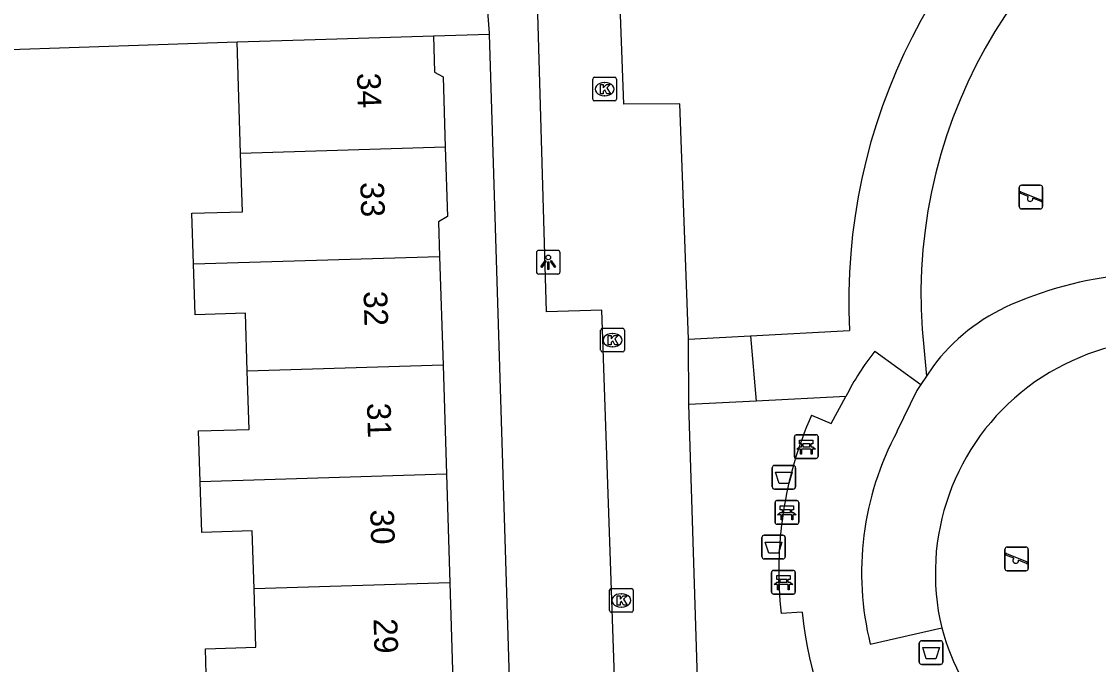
# Model space of a CAD drawing. Extents: x 162250 to 162654, y 380744 to 381605.
# Drawn here: x 162347.75 to 162393.23, y 381155.14 to 381182.3 of the extents above; entities that cross this region are included whole.
import ezdxf

# ---------------------------------------------------------------- set-up
doc = ezdxf.new("R2010")
doc.units = 0
for name, color, linetype in [('IMGEO_Afvalbak', 7, 'Continuous'), ('IMGEO_Bank', 7, 'Continuous'), ('IMGEO_Groenvoorziening', 7, 'Continuous'), ('IMGEO_Kolk', 7, 'Continuous'), ('IMGEO_Lichtpunt', 7, 'Continuous'), ('IMGEO_Pand', 7, 'Continuous'), ('IMGEO_Pand_nummerreeks', 7, 'Continuous'), ('IMGEO_Speelvoorziening', 7, 'Continuous'), ('IMGEO_Voetpad_open', 7, 'Continuous'), ('IMGEO_Woonerf_open', 7, 'Continuous')]:
    doc.layers.add(name, color=color, linetype=linetype)

msp = doc.modelspace()

# ---------------------------------------------------------------- linework, layer by layer
at = {"layer": 'IMGEO_Afvalbak'}
for p, q in [((162379.45, 381162.647), (162379.45, 381163.447)), ((162379.45, 381163.447), (162379.45, 381162.647)), ((162379.55, 381163.547), (162380.34, 381163.547)), ((162380.34, 381163.547), (162379.55, 381163.547)), ((162380.44, 381163.447), (162380.44, 381162.647)), ((162380.44, 381162.647), (162380.44, 381163.447)), ((162380.34, 381162.547), (162379.55, 381162.547)), ((162379.55, 381162.547), (162380.34, 381162.547)), ((162379.013, 381159.698), (162379.013, 381160.498)), ((162379.013, 381160.498), (162379.013, 381159.698)), ((162379.113, 381160.598), (162379.903, 381160.598)), ((162379.903, 381160.598), (162379.113, 381160.598)), ((162380.003, 381160.498), (162380.003, 381159.698)), ((162380.003, 381159.698), (162380.003, 381160.498)), ((162379.903, 381159.598), (162379.113, 381159.598)), ((162379.113, 381159.598), (162379.903, 381159.598)), ((162385.764, 381156.138), (162386.554, 381156.138)), ((162386.554, 381156.138), (162385.764, 381156.138)), ((162385.664, 381155.238), (162385.664, 381156.038)), ((162385.664, 381156.038), (162385.664, 381155.238)), ((162386.654, 381156.038), (162386.654, 381155.238)), ((162386.654, 381155.238), (162386.654, 381156.038)), ((162386.554, 381155.138), (162385.764, 381155.138)), ((162385.764, 381155.138), (162386.554, 381155.138))]:
    msp.add_line(p, q, dxfattribs=at)
for points in [[(162379.593, 381163.261), (162380.297, 381163.261), (162380.148, 381162.791), (162379.742, 381162.791), (162379.593, 381163.261)], [(162379.156, 381160.312), (162379.86, 381160.312), (162379.711, 381159.842), (162379.305, 381159.842), (162379.156, 381160.312)], [(162385.807, 381155.852), (162386.511, 381155.852), (162386.362, 381155.382), (162385.956, 381155.382), (162385.807, 381155.852)]]:
    msp.add_lwpolyline(points, dxfattribs=at)
for centre, start, end in [((162379.55, 381163.447), 90, 180), ((162379.55, 381163.447), 90, 180), ((162380.34, 381163.447), 0, 90), ((162380.34, 381163.447), 360, 90), ((162379.55, 381162.647), 180, 270), ((162379.55, 381162.647), 180, 270), ((162380.34, 381162.647), 270, 0), ((162380.34, 381162.647), 270, 0), ((162379.113, 381160.498), 90, 180), ((162379.113, 381160.498), 90, 180), ((162379.903, 381160.498), 0, 90), ((162379.903, 381160.498), 360, 90), ((162379.113, 381159.698), 180, 270), ((162379.113, 381159.698), 180, 270), ((162379.903, 381159.698), 270, 0), ((162379.903, 381159.698), 270, 0), ((162385.764, 381156.038), 90, 180), ((162385.764, 381156.038), 90, 180), ((162386.554, 381156.038), 0, 90), ((162386.554, 381156.038), 360, 90), ((162385.764, 381155.238), 180, 270), ((162385.764, 381155.238), 180, 270), ((162386.554, 381155.238), 270, 0), ((162386.554, 381155.238), 270, 0)]:
    msp.add_arc(centre, 0.1, start, end, dxfattribs=at)
at = {"layer": 'IMGEO_Bank'}
for p, q in [((162380.462, 381164.84), (162381.303, 381164.84)), ((162381.303, 381164.84), (162380.462, 381164.84)), ((162380.387, 381163.915), (162380.387, 381164.756)), ((162380.387, 381164.756), (162380.387, 381163.915)), ((162380.696, 381164.346), (162380.696, 381164.452)), ((162380.74, 381164.452), (162380.74, 381164.346)), ((162381.028, 381164.458), (162380.746, 381164.458)), ((162380.746, 381164.34), (162381.028, 381164.34)), ((162381.034, 381164.346), (162381.034, 381164.452)), ((162381.078, 381164.452), (162381.078, 381164.346)), ((162381.387, 381164.765), (162381.387, 381163.924)), ((162381.387, 381163.924), (162381.387, 381164.765)), ((162381.084, 381164.238), (162380.691, 381164.238)), ((162381.312, 381163.84), (162380.471, 381163.84)), ((162380.471, 381163.84), (162381.312, 381163.84)), ((162379.647, 381162.06), (162380.488, 381162.06)), ((162380.488, 381162.06), (162379.647, 381162.06)), ((162379.572, 381161.135), (162379.572, 381161.976)), ((162379.572, 381161.976), (162379.572, 381161.135)), ((162379.881, 381161.566), (162379.881, 381161.672)), ((162379.925, 381161.672), (162379.925, 381161.566)), ((162380.213, 381161.678), (162379.931, 381161.678)), ((162380.219, 381161.566), (162380.219, 381161.672)), ((162380.263, 381161.672), (162380.263, 381161.566)), ((162380.572, 381161.985), (162380.572, 381161.144)), ((162380.572, 381161.144), (162380.572, 381161.985)), ((162380.269, 381161.458), (162379.876, 381161.458)), ((162379.931, 381161.56), (162380.213, 381161.56)), ((162380.497, 381161.06), (162379.656, 381161.06)), ((162379.656, 381161.06), (162380.497, 381161.06)), ((162379.424, 381158.188), (162379.424, 381159.029)), ((162379.424, 381159.029), (162379.424, 381158.188)), ((162379.499, 381159.113), (162380.34, 381159.113)), ((162380.34, 381159.113), (162379.499, 381159.113)), ((162380.424, 381159.038), (162380.424, 381158.197)), ((162380.424, 381158.197), (162380.424, 381159.038)), ((162380.121, 381158.511), (162379.728, 381158.511)), ((162379.733, 381158.619), (162379.733, 381158.725)), ((162379.777, 381158.725), (162379.777, 381158.619)), ((162380.065, 381158.731), (162379.783, 381158.731)), ((162379.783, 381158.613), (162380.065, 381158.613)), ((162380.071, 381158.619), (162380.071, 381158.725)), ((162380.115, 381158.725), (162380.115, 381158.619)), ((162380.349, 381158.113), (162379.508, 381158.113)), ((162379.508, 381158.113), (162380.349, 381158.113))]:
    msp.add_line(p, q, dxfattribs=at)
for points in [[(162380.634, 381164.238), (162380.492, 381164.238), (162380.604, 381164.34), (162380.69, 381164.34)], [(162380.69, 381164.458), (162380.604, 381164.458), (162380.604, 381164.619), (162381.167, 381164.619), (162381.167, 381164.458), (162381.084, 381164.458)], [(162381.084, 381164.34), (162381.167, 381164.34), (162381.279, 381164.238), (162381.14, 381164.238)], [(162380.684, 381164.231), (162380.684, 381164.024), (162380.641, 381164.024), (162380.641, 381164.231)], [(162381.134, 381164.231), (162381.134, 381164.024), (162381.09, 381164.024), (162381.09, 381164.231)], [(162379.875, 381161.678), (162379.789, 381161.678), (162379.789, 381161.839), (162380.352, 381161.839), (162380.352, 381161.678), (162380.269, 381161.678)], [(162379.819, 381161.458), (162379.677, 381161.458), (162379.789, 381161.56), (162379.875, 381161.56)], [(162379.869, 381161.451), (162379.869, 381161.244), (162379.826, 381161.244), (162379.826, 381161.451)], [(162380.269, 381161.56), (162380.352, 381161.56), (162380.464, 381161.458), (162380.325, 381161.458)], [(162380.319, 381161.451), (162380.319, 381161.244), (162380.275, 381161.244), (162380.275, 381161.451)], [(162379.727, 381158.731), (162379.641, 381158.731), (162379.641, 381158.892), (162380.204, 381158.892), (162380.204, 381158.731), (162380.121, 381158.731)], [(162379.671, 381158.511), (162379.529, 381158.511), (162379.641, 381158.613), (162379.727, 381158.613)], [(162379.721, 381158.504), (162379.721, 381158.297), (162379.678, 381158.297), (162379.678, 381158.504)], [(162380.121, 381158.613), (162380.204, 381158.613), (162380.316, 381158.511), (162380.177, 381158.511)], [(162380.171, 381158.504), (162380.171, 381158.297), (162380.127, 381158.297), (162380.127, 381158.504)]]:
    msp.add_lwpolyline(points, dxfattribs=at)
for centre, radius, start, end in [((162380.465, 381164.762), 0.0779, 92.4484, 184.2845), ((162380.465, 381164.762), 0.0779, 92.4484, 184.2845), ((162381.309, 381164.762), 0.0779, 2.4484, 94.2845), ((162381.309, 381164.762), 0.0779, 2.4484, 94.2845), ((162380.689, 381164.451), 0.00671, 2.8957, 87.1043), ((162380.689, 381164.347), 0.00671, 272.8957, 357.1043), ((162380.746, 381164.451), 0.00671, 92.8957, 177.1043), ((162380.746, 381164.347), 0.00671, 182.8957, 267.1043), ((162381.028, 381164.451), 0.00671, 2.8957, 87.1043), ((162381.028, 381164.347), 0.00671, 272.8957, 357.1043), ((162381.085, 381164.451), 0.00671, 92.8957, 177.1043), ((162381.085, 381164.347), 0.00671, 182.8957, 267.1043), ((162380.465, 381163.918), 0.0779, 182.4484, 274.2845), ((162380.465, 381163.918), 0.0779, 182.4484, 274.2845), ((162380.634, 381164.231), 0.00671, 2.8957, 87.1043), ((162380.691, 381164.231), 0.00671, 92.8957, 177.1043), ((162381.083, 381164.231), 0.00671, 2.8957, 87.1043), ((162381.14, 381164.231), 0.00671, 92.8957, 177.1043), ((162381.309, 381163.918), 0.0779, 272.4484, 4.2845), ((162381.309, 381163.918), 0.0779, 272.4484, 4.2845), ((162379.65, 381161.982), 0.0779, 92.4484, 184.2845), ((162379.65, 381161.982), 0.0779, 92.4484, 184.2845), ((162380.494, 381161.982), 0.0779, 2.4484, 94.2845), ((162380.494, 381161.982), 0.0779, 2.4484, 94.2845), ((162379.874, 381161.671), 0.00671, 2.8957, 87.1043), ((162379.931, 381161.671), 0.00671, 92.8957, 177.1043), ((162380.213, 381161.671), 0.00671, 2.8957, 87.1043), ((162380.27, 381161.671), 0.00671, 92.8957, 177.1043), ((162379.65, 381161.138), 0.0779, 182.4484, 274.2845), ((162379.65, 381161.138), 0.0779, 182.4484, 274.2845), ((162379.819, 381161.451), 0.00671, 2.8957, 87.1043), ((162379.876, 381161.451), 0.00671, 92.8957, 177.1043), ((162379.874, 381161.567), 0.00671, 272.8957, 357.1043), ((162379.931, 381161.567), 0.00671, 182.8957, 267.1043), ((162380.213, 381161.567), 0.00671, 272.8957, 357.1043), ((162380.27, 381161.567), 0.00671, 182.8957, 267.1043), ((162380.268, 381161.451), 0.00671, 2.8957, 87.1043), ((162380.325, 381161.451), 0.00671, 92.8957, 177.1043), ((162380.494, 381161.138), 0.0779, 272.4484, 4.2845), ((162380.494, 381161.138), 0.0779, 272.4484, 4.2845), ((162379.502, 381159.035), 0.0779, 92.4484, 184.2845), ((162379.502, 381159.035), 0.0779, 92.4484, 184.2845), ((162380.346, 381159.035), 0.0779, 2.4484, 94.2845), ((162380.346, 381159.035), 0.0779, 2.4484, 94.2845), ((162379.671, 381158.504), 0.00671, 2.8957, 87.1043), ((162379.728, 381158.504), 0.00671, 92.8957, 177.1043), ((162379.726, 381158.724), 0.00671, 2.8957, 87.1043), ((162379.726, 381158.62), 0.00671, 272.8957, 357.1043), ((162379.783, 381158.724), 0.00671, 92.8957, 177.1043), ((162379.783, 381158.62), 0.00671, 182.8957, 267.1043), ((162380.065, 381158.724), 0.00671, 2.8957, 87.1043), ((162380.065, 381158.62), 0.00671, 272.8957, 357.1043), ((162380.122, 381158.724), 0.00671, 92.8957, 177.1043), ((162380.122, 381158.62), 0.00671, 182.8957, 267.1043), ((162380.12, 381158.504), 0.00671, 2.8957, 87.1043), ((162380.177, 381158.504), 0.00671, 92.8957, 177.1043), ((162379.502, 381158.191), 0.0779, 182.4484, 274.2845), ((162379.502, 381158.191), 0.0779, 182.4484, 274.2845), ((162380.346, 381158.191), 0.0779, 272.4484, 4.2845), ((162380.346, 381158.191), 0.0779, 272.4484, 4.2845)]:
    msp.add_arc(centre, radius, start, end, dxfattribs=at)
at = {"layer": 'IMGEO_Groenvoorziening'}
msp.add_lwpolyline([(162386.231, 381167.71), (162385.966, 381167.313)], dxfattribs=at)
for centre, radius, start, end in [((162395.874, 381155.908), 15.758, 74.4551, 113.6675), ((162392.818, 381162.811), 8.209, 113.4773, 143.3646), ((162396.219, 381158.985), 9.879, 354.6001, 193.4375)]:
    msp.add_arc(centre, radius, start, end, dxfattribs=at)
at = {"layer": 'IMGEO_Kolk'}
for p, q in [((162371.873, 381179.019), (162371.873, 381179.871)), ((162371.948, 381179.945), (162372.8, 381179.945)), ((162372.874, 381179.871), (162372.874, 381179.019)), ((162372.361, 381179.725), (162372.386, 381179.725)), ((162372.8, 381178.945), (162371.948, 381178.945)), ((162372.384, 381179.165), (162372.359, 381179.165)), ((162372.281, 381169.342), (162373.133, 381169.342)), ((162372.206, 381168.416), (162372.206, 381169.268)), ((162372.694, 381169.122), (162372.719, 381169.122)), ((162373.207, 381169.268), (162373.207, 381168.416)), ((162372.717, 381168.562), (162372.692, 381168.562)), ((162373.133, 381168.342), (162372.281, 381168.342)), ((162372.582, 381157.419), (162372.582, 381158.271)), ((162372.657, 381158.345), (162373.509, 381158.345)), ((162373.07, 381158.125), (162373.095, 381158.125)), ((162373.583, 381158.271), (162373.583, 381157.419)), ((162373.093, 381157.565), (162373.068, 381157.565)), ((162373.509, 381157.345), (162372.657, 381157.345))]:
    msp.add_line(p, q, dxfattribs=at)
for points in [[(162371.873, 381179.019), (162371.873, 381179.871)], [(162371.948, 381179.945), (162372.8, 381179.945)], [(162372.874, 381179.871), (162372.874, 381179.019)], [(162372.194, 381179.645), (162372.317, 381179.645), (162372.317, 381179.494), (162372.447, 381179.645), (162372.611, 381179.645), (162372.465, 381179.494), (162372.618, 381179.245), (162372.466, 381179.245), (162372.381, 381179.409), (162372.317, 381179.342), (162372.317, 381179.245), (162372.194, 381179.245), (162372.194, 381179.645)], [(162372.8, 381178.945), (162371.948, 381178.945)], [(162372.281, 381169.342), (162373.133, 381169.342)], [(162372.206, 381168.416), (162372.206, 381169.268)], [(162372.527, 381169.042), (162372.65, 381169.042), (162372.65, 381168.891), (162372.78, 381169.042), (162372.944, 381169.042), (162372.798, 381168.891), (162372.951, 381168.642), (162372.799, 381168.642), (162372.714, 381168.806), (162372.65, 381168.739), (162372.65, 381168.642), (162372.527, 381168.642), (162372.527, 381169.042)], [(162373.207, 381169.268), (162373.207, 381168.416)], [(162373.133, 381168.342), (162372.281, 381168.342)], [(162372.582, 381157.419), (162372.582, 381158.271)], [(162372.657, 381158.345), (162373.509, 381158.345)], [(162372.903, 381158.045), (162373.026, 381158.045), (162373.026, 381157.894), (162373.156, 381158.045), (162373.32, 381158.045), (162373.174, 381157.894), (162373.327, 381157.645), (162373.175, 381157.645), (162373.09, 381157.809), (162373.026, 381157.742), (162373.026, 381157.645), (162372.903, 381157.645), (162372.903, 381158.045)], [(162373.583, 381158.271), (162373.583, 381157.419)], [(162373.509, 381157.345), (162372.657, 381157.345)]]:
    msp.add_lwpolyline(points, dxfattribs=at)
for centre, start, end in [((162371.95, 381179.869), 91.552, 178.448), ((162371.95, 381179.869), 91.552, 178.448), ((162372.798, 381179.869), 1.552, 88.448), ((162372.798, 381179.869), 1.552, 88.448), ((162371.95, 381179.021), 181.552, 268.448), ((162371.95, 381179.021), 181.552, 268.448), ((162372.798, 381179.021), 271.552, 358.448), ((162372.798, 381179.021), 271.552, 358.448), ((162372.283, 381169.266), 91.552, 178.448), ((162372.283, 381169.266), 91.552, 178.448), ((162373.131, 381169.266), 1.552, 88.448), ((162373.131, 381169.266), 1.552, 88.448), ((162372.283, 381168.418), 181.552, 268.448), ((162372.283, 381168.418), 181.552, 268.448), ((162373.131, 381168.418), 271.552, 358.448), ((162373.131, 381168.418), 271.552, 358.448), ((162372.659, 381158.269), 91.552, 178.448), ((162372.659, 381158.269), 91.552, 178.448), ((162373.507, 381158.269), 1.552, 88.448), ((162373.507, 381158.269), 1.552, 88.448), ((162372.659, 381157.421), 181.552, 268.448), ((162372.659, 381157.421), 181.552, 268.448), ((162373.507, 381157.421), 271.552, 358.448), ((162373.507, 381157.421), 271.552, 358.448)]:
    msp.add_arc(centre, 0.0765, start, end, dxfattribs=at)
for centre, major_axis, ratio, start_param, end_param in [((162372.36, 381179.445), (-0.387, 0.002), 0.722429, 4.712389, 7.853982), ((162372.385, 381179.445), (-0.39, 0.002), 0.717154, 1.570796, 4.712389), ((162372.693, 381168.842), (-0.387, 0.002), 0.722429, 4.712389, 7.853982), ((162372.718, 381168.842), (-0.39, 0.002), 0.717154, 1.570796, 4.712389), ((162373.069, 381157.845), (-0.387, 0.002), 0.722429, 4.712389, 7.853982), ((162373.094, 381157.845), (-0.39, 0.002), 0.717154, 1.570796, 4.712389)]:
    msp.add_ellipse(centre, major_axis=major_axis, ratio=ratio, start_param=start_param, end_param=end_param, dxfattribs=at)
at = {"layer": 'IMGEO_Lichtpunt'}
for p, q in [((162369.495, 381172.536), (162369.495, 381171.729)), ((162369.495, 381172.536), (162369.495, 381171.729)), ((162370.397, 381172.631), (162369.589, 381172.631)), ((162370.397, 381172.631), (162369.589, 381172.631)), ((162370.491, 381171.729), (162370.491, 381172.536)), ((162370.491, 381171.729), (162370.491, 381172.536)), ((162369.589, 381171.635), (162370.397, 381171.635)), ((162369.589, 381171.635), (162370.397, 381171.635))]:
    msp.add_line(p, q, dxfattribs=at)
for points in [[(162369.869, 381172.2), (162369.908, 381172.172), (162369.72, 381171.91), (162369.682, 381171.937), (162369.869, 381172.2)], [(162369.971, 381172.152), (162370.018, 381172.152), (162370.018, 381171.83), (162369.971, 381171.83), (162369.971, 381172.152)], [(162370.081, 381172.172), (162370.119, 381172.199), (162370.306, 381171.937), (162370.267, 381171.909), (162370.081, 381172.172)]]:
    msp.add_lwpolyline(points, dxfattribs=at)
msp.add_circle((162369.994, 381172.334), 0.0994, dxfattribs=at)
for centre, start, end in [((162369.589, 381172.536), 90, 180), ((162369.589, 381172.536), 90, 180), ((162370.397, 381172.536), 0, 90), ((162370.397, 381172.536), 0, 90), ((162369.589, 381171.729), 180, 270), ((162369.589, 381171.729), 180, 270), ((162370.397, 381171.729), 270, 0), ((162370.397, 381171.729), 270, 360)]:
    msp.add_arc(centre, 0.0946, start, end, dxfattribs=at)
at = {"layer": 'IMGEO_Pand'}
for points in [[(162356.853, 381181.442), (162360.148, 381181.544), (162365.145, 381181.699)], [(162365.145, 381181.699), (162365.193, 381180.16), (162365.548, 381179.969), (162365.64, 381176.992)], [(162356.999, 381176.724), (162356.853, 381181.442)], [(162355.01, 381172.059), (162354.943, 381174.202), (162357.075, 381174.268), (162356.999, 381176.724)], [(162365.64, 381176.992), (162356.999, 381176.724)], [(162365.64, 381176.992), (162365.731, 381174.069), (162365.36, 381173.839), (162365.405, 381172.381)], [(162355.01, 381172.059), (162365.405, 381172.381)], [(162357.284, 381167.526), (162357.208, 381169.982), (162355.076, 381169.916), (162355.01, 381172.059)], [(162365.405, 381172.381), (162365.548, 381167.782)], [(162355.294, 381162.861), (162355.227, 381165.004), (162357.36, 381165.07), (162357.284, 381167.526)], [(162365.548, 381167.782), (162357.284, 381167.526)], [(162365.548, 381167.782), (162365.69, 381163.184)], [(162365.69, 381163.184), (162355.294, 381162.861)], [(162365.69, 381163.184), (162365.833, 381158.585)], [(162357.569, 381158.328), (162357.493, 381160.784), (162355.36, 381160.718), (162355.294, 381162.861)], [(162365.833, 381158.585), (162357.569, 381158.328)], [(162365.833, 381158.585), (162365.975, 381153.986)], [(162355.579, 381153.663), (162355.512, 381155.806), (162357.645, 381155.872), (162357.569, 381158.328)]]:
    msp.add_lwpolyline(points, dxfattribs=at)
at = {"layer": 'IMGEO_Speelvoorziening'}
for p, q in [((162389.883, 381174.486), (162389.883, 381175.286)), ((162389.883, 381175.286), (162389.883, 381174.486)), ((162389.983, 381175.386), (162390.773, 381175.386)), ((162390.773, 381175.386), (162389.983, 381175.386)), ((162390.873, 381175.286), (162390.873, 381174.486)), ((162390.873, 381174.486), (162390.873, 381175.286)), ((162390.266, 381174.914), (162389.927, 381175.051)), ((162389.952, 381175.111), (162390.828, 381174.758)), ((162390.804, 381174.698), (162390.464, 381174.835)), ((162390.773, 381174.386), (162389.983, 381174.386)), ((162389.983, 381174.386), (162390.773, 381174.386)), ((162389.276, 381159.196), (162389.276, 381159.996)), ((162389.276, 381159.996), (162389.276, 381159.196)), ((162389.345, 381159.821), (162390.221, 381159.468)), ((162389.376, 381160.096), (162390.166, 381160.096)), ((162390.166, 381160.096), (162389.376, 381160.096)), ((162390.266, 381159.996), (162390.266, 381159.196)), ((162390.266, 381159.196), (162390.266, 381159.996)), ((162389.659, 381159.624), (162389.32, 381159.761)), ((162390.197, 381159.408), (162389.857, 381159.545)), ((162390.166, 381159.096), (162389.376, 381159.096)), ((162389.376, 381159.096), (162390.166, 381159.096))]:
    msp.add_line(p, q, dxfattribs=at)
for centre, radius, start, end in [((162389.983, 381175.286), 0.1, 90, 180), ((162389.983, 381175.286), 0.1, 90, 180), ((162390.773, 381175.286), 0.1, 0, 90), ((162390.773, 381175.286), 0.1, 360, 90), ((162389.94, 381175.081), 0.0327, 68.078, 248.078), ((162390.345, 381174.824), 0.12, 130.9928, 5.1632), ((162389.983, 381174.486), 0.1, 180, 270), ((162389.983, 381174.486), 0.1, 180, 270), ((162390.773, 381174.486), 0.1, 270, 0), ((162390.773, 381174.486), 0.1, 270, 0), ((162390.816, 381174.728), 0.0327, 248.078, 68.078), ((162389.376, 381159.996), 0.1, 90, 180), ((162389.376, 381159.996), 0.1, 90, 180), ((162389.333, 381159.791), 0.0327, 68.078, 248.078), ((162390.166, 381159.996), 0.1, 0, 90), ((162390.166, 381159.996), 0.1, 360, 90), ((162389.738, 381159.534), 0.12, 130.9928, 5.1632), ((162390.209, 381159.438), 0.0327, 248.078, 68.078), ((162389.376, 381159.196), 0.1, 180, 270), ((162389.376, 381159.196), 0.1, 180, 270), ((162390.166, 381159.196), 0.1, 270, 0), ((162390.166, 381159.196), 0.1, 270, 0)]:
    msp.add_arc(centre, radius, start, end, dxfattribs=at)
at = {"layer": 'IMGEO_Voetpad_open'}
for points in [[(162371.488, 381120.602), (162370.442, 381153.711), (162372.814, 381153.789), (162372.262, 381170.102), (162369.918, 381170.032), (162369.115, 381197.654)], [(162367.515, 381181.772), (162367.514, 381181.806), (162367.369, 381183.635)], [(162365.145, 381181.699), (162367.515, 381181.772)], [(162369.33, 381123.227), (162367.515, 381181.772)], [(162346.828, 381181.107), (162356.853, 381181.442)], [(162375.911, 381168.88), (162378.53, 381169.022)], [(162375.937, 381166.122), (162375.911, 381168.88)], [(162378.53, 381169.022), (162382.72, 381169.249)], [(162378.53, 381169.022), (162378.778, 381166.268)], [(162385.779, 381169.305), (162385.966, 381167.313)], [(162383.791, 381168.377), (162385.732, 381166.96)], [(162385.966, 381167.313), (162385.732, 381166.96)], [(162385.732, 381166.96), (162385.565, 381166.71), (162384.721, 381164.979)], [(162378.778, 381166.268), (162375.937, 381166.122)], [(162382.564, 381166.463), (162378.778, 381166.268)], [(162381.112, 381165.674), (162381.944, 381165.318), (162382.564, 381166.463)], [(162380.72, 381157.348), (162379.826, 381157.293)], [(162383.593, 381155.993), (162386.611, 381156.689)]]:
    msp.add_lwpolyline(points, dxfattribs=at)
for centre, radius, start, end in [((162407.245, 381170.506), 24.557, 123.109, 182.9344), ((162407.113, 381170.744), 21.382, 113.3729, 183.8578), ((162392.603, 381161.378), 11.254, 141.54, 153.1349), ((162396.1, 381159.085), 16.372, 156.2689, 186.284), ((162395.833, 381159.02), 12.608, 151.7975, 193.8928), ((162395.619, 381158.684), 14.958, 185.1237, 214.9772), ((162396.682, 381159.39), 10.427, 195.0151, 247.5623)]:
    msp.add_arc(centre, radius, start, end, dxfattribs=at)
at = {"layer": 'IMGEO_Woonerf_open'}
for points in [[(162375.911, 381168.88), (162375.907, 381169.266), (162375.553, 381178.828), (162373.184, 381178.813), (162372.856, 381187.495), (162373.842, 381187.531)], [(162376.436, 381150.082), (162375.937, 381166.122)]]:
    msp.add_lwpolyline(points, dxfattribs=at)

# ---------------------------------------------------------------- texts
at = {"layer": 'IMGEO_Pand_nummerreeks'}
for s, p in [('34', (162361.911, 381180.121)), ('33', (162362.052, 381175.511)), ('32', (162362.191, 381170.904)), ('31', (162362.335, 381166.178)), ('30', (162362.473, 381161.678)), ('29', (162362.613, 381157.072))]:
    msp.add_text(s, height=1, rotation=271.7429, dxfattribs=at).set_placement(p)

doc.saveas('drawing.dxf')
